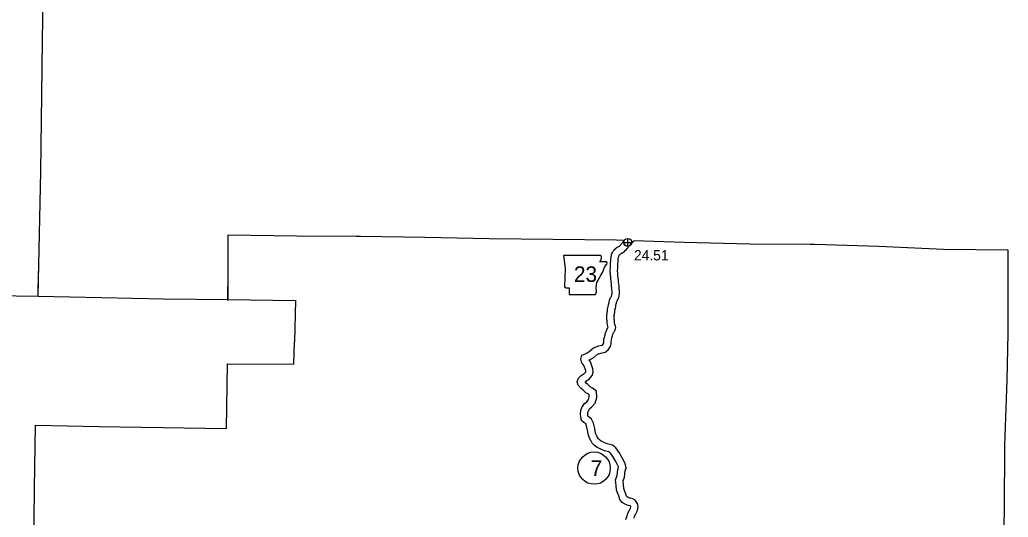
# Model space of a CAD drawing. Extents: x -939622 to -934245, y 1383184 to 1385301.
# Drawn here: x -936241.4 to -936120.4, y 1384764 to 1384824.9 of the extents above; entities that cross this region are included whole.
import ezdxf

# ---------------------------------------------------------------- set-up
doc = ezdxf.new("R2010")
doc.units = 0
for name, color, linetype in [('2', 7, 'Continuous'), ('Level 10', 7, 'Continuous'), ('Level 2', 7, 'Continuous'), ('Level 21', 7, 'Continuous'), ('Level 25', 7, 'Continuous'), ('Level 26', 7, 'Continuous'), ('Level 27', 7, 'Continuous')]:
    doc.layers.add(name, color=color, linetype=linetype)

msp = doc.modelspace()

# ---------------------------------------------------------------- linework, layer by layer
at = {"layer": '2'}
msp.add_lwpolyline([(-936255.7, 1384791.16), (-936244.58, 1384791.15), (-936239.18, 1384791.06), (-936238.82, 1384806.34), (-936238.71, 1384815.74), (-936238.65, 1384822.33), (-936238.51, 1384830.53), (-936234.63, 1384830.51), (-936234.25, 1384853.43)], dxfattribs=at)
at = {"layer": 'Level 10'}
for points in [[(-936169.88, 1384785.79), (-936169.74, 1384786.3), (-936169.71, 1384786.44), (-936169.67, 1384786.57), (-936169.61, 1384786.73), (-936169.57, 1384786.85), (-936169.52, 1384786.99), (-936169.45, 1384787.12), (-936169.38, 1384787.23), (-936169.36, 1384787.25), (-936169.4, 1384787.36), (-936169.46, 1384787.6), (-936169.47, 1384787.76), (-936169.49, 1384787.92), (-936169.5, 1384788.05), (-936169.51, 1384788.16), (-936169.53, 1384788.33), (-936169.53, 1384788.5), (-936169.52, 1384788.65), (-936169.51, 1384788.8), (-936169.48, 1384788.94), (-936169.47, 1384789.1), (-936169.45, 1384789.21), (-936169.44, 1384789.31), (-936169.42, 1384789.48), (-936169.39, 1384789.65), (-936169.35, 1384789.81), (-936169.32, 1384789.94), (-936169.3, 1384790.04), (-936169.28, 1384790.17), (-936169.25, 1384790.3), (-936169.22, 1384790.42), (-936169.18, 1384790.56), (-936169.15, 1384790.69), (-936169.1, 1384790.8), (-936169.04, 1384790.9), (-936169.01, 1384790.98), (-936168.97, 1384791.07), (-936168.93, 1384791.15), (-936168.91, 1384791.21), (-936168.89, 1384791.27), (-936168.88, 1384791.31), (-936168.88, 1384791.33), (-936168.88, 1384791.41), (-936168.88, 1384791.68), (-936168.89, 1384791.85), (-936168.92, 1384792.1), (-936168.93, 1384792.29), (-936168.94, 1384792.43), (-936168.96, 1384792.62), (-936168.99, 1384792.78), (-936169.01, 1384792.94), (-936169.02, 1384793.13), (-936169.03, 1384793.27), (-936169.05, 1384793.41), (-936169.07, 1384793.56), (-936169.08, 1384793.72), (-936169.09, 1384793.85), (-936169.1, 1384793.97), (-936169.12, 1384794.12), (-936169.11, 1384794.31), (-936169.09, 1384794.48), (-936169.08, 1384794.7), (-936169.06, 1384795.05), (-936169.03, 1384795.43), (-936169.02, 1384795.63), (-936169.01, 1384795.78), (-936168.99, 1384795.94), (-936168.96, 1384796.05), (-936168.93, 1384796.15), (-936168.9, 1384796.27), (-936168.84, 1384796.41), (-936168.75, 1384796.59), (-936168.63, 1384796.71), (-936168.55, 1384796.81), (-936168.44, 1384796.89), (-936168.4, 1384796.94), (-936168.28, 1384797.03), (-936168.18, 1384797.1), (-936168.09, 1384797.15), (-936167.99, 1384797.19), (-936167.98, 1384797.2), (-936167.95, 1384797.24), (-936167.86, 1384797.32), (-936167.8, 1384797.38), (-936167.76, 1384797.44), (-936167.7, 1384797.51), (-936167.64, 1384797.59), (-936167.58, 1384797.67), (-936167.51, 1384797.75), (-936167.45, 1384797.83), (-936167.4, 1384797.9)], [(-936168.99, 1384785.49), (-936168.9, 1384785.96), (-936168.87, 1384786.07), (-936168.84, 1384786.19), (-936168.81, 1384786.3), (-936168.76, 1384786.44), (-936168.73, 1384786.55), (-936168.7, 1384786.63), (-936168.68, 1384786.66), (-936168.64, 1384786.72), (-936168.59, 1384786.79), (-936168.56, 1384786.84), (-936168.53, 1384786.88), (-936168.47, 1384786.99), (-936168.45, 1384787.09), (-936168.44, 1384787.22), (-936168.46, 1384787.37), (-936168.53, 1384787.6), (-936168.57, 1384787.75), (-936168.58, 1384787.86), (-936168.6, 1384787.99), (-936168.6, 1384788.12), (-936168.62, 1384788.25), (-936168.63, 1384788.38), (-936168.63, 1384788.48), (-936168.62, 1384788.58), (-936168.61, 1384788.69), (-936168.59, 1384788.82), (-936168.58, 1384788.97), (-936168.55, 1384789.09), (-936168.54, 1384789.22), (-936168.53, 1384789.35), (-936168.51, 1384789.47), (-936168.47, 1384789.61), (-936168.44, 1384789.76), (-936168.41, 1384789.89), (-936168.4, 1384789.99), (-936168.38, 1384790.09), (-936168.35, 1384790.2), (-936168.32, 1384790.32), (-936168.3, 1384790.38), (-936168.28, 1384790.41), (-936168.24, 1384790.51), (-936168.19, 1384790.61), (-936168.15, 1384790.7), (-936168.1, 1384790.8), (-936168.06, 1384790.92), (-936168.03, 1384791.02), (-936168, 1384791.13), (-936167.98, 1384791.3), (-936167.98, 1384791.44), (-936167.98, 1384791.71), (-936168, 1384791.92), (-936168.02, 1384792.16), (-936168.03, 1384792.35), (-936168.04, 1384792.53), (-936168.08, 1384792.76), (-936168.1, 1384792.9), (-936168.11, 1384793.02), (-936168.13, 1384793.21), (-936168.14, 1384793.36), (-936168.16, 1384793.51), (-936168.17, 1384793.65), (-936168.19, 1384793.79), (-936168.19, 1384793.92), (-936168.21, 1384794.07), (-936168.22, 1384794.14), (-936168.21, 1384794.24), (-936168.19, 1384794.41), (-936168.18, 1384794.64), (-936168.16, 1384794.99), (-936168.13, 1384795.37), (-936168.12, 1384795.58), (-936168.12, 1384795.69), (-936168.11, 1384795.75), (-936168.09, 1384795.82), (-936168.07, 1384795.91), (-936168.05, 1384795.96), (-936168.02, 1384796.03), (-936168, 1384796.07), (-936167.96, 1384796.11), (-936167.92, 1384796.16), (-936167.85, 1384796.22), (-936167.8, 1384796.26), (-936167.76, 1384796.3), (-936167.72, 1384796.32), (-936167.67, 1384796.35), (-936167.6, 1384796.38), (-936167.48, 1384796.44), (-936167.35, 1384796.55), (-936167.27, 1384796.64), (-936167.22, 1384796.7), (-936167.13, 1384796.78), (-936167.05, 1384796.88), (-936166.99, 1384796.96), (-936166.92, 1384797.04), (-936166.87, 1384797.12), (-936166.81, 1384797.19), (-936166.74, 1384797.28), (-936166.69, 1384797.35)], [(-936168.91, 1384785.95), (-936168.9, 1384785.96), (-936168.87, 1384786.07), (-936168.84, 1384786.19), (-936168.81, 1384786.3), (-936168.76, 1384786.44), (-936168.73, 1384786.55), (-936168.7, 1384786.63), (-936168.68, 1384786.66), (-936168.64, 1384786.72), (-936168.59, 1384786.79), (-936168.56, 1384786.84), (-936168.53, 1384786.88), (-936168.47, 1384786.99), (-936168.45, 1384787.09), (-936168.44, 1384787.22), (-936168.46, 1384787.37), (-936168.53, 1384787.6), (-936168.57, 1384787.75), (-936168.58, 1384787.86), (-936168.6, 1384787.99), (-936168.6, 1384788.12), (-936168.62, 1384788.25), (-936168.63, 1384788.38), (-936168.63, 1384788.48), (-936168.62, 1384788.58), (-936168.61, 1384788.69), (-936168.59, 1384788.82), (-936168.58, 1384788.97), (-936168.55, 1384789.09), (-936168.54, 1384789.22), (-936168.53, 1384789.35), (-936168.51, 1384789.47), (-936168.47, 1384789.61), (-936168.44, 1384789.76), (-936168.41, 1384789.89), (-936168.4, 1384789.99), (-936168.38, 1384790.09), (-936168.35, 1384790.2), (-936168.32, 1384790.32), (-936168.3, 1384790.38), (-936168.28, 1384790.41), (-936168.24, 1384790.51), (-936168.19, 1384790.61), (-936168.15, 1384790.7), (-936168.1, 1384790.8), (-936168.06, 1384790.92), (-936168.03, 1384791.02), (-936168, 1384791.13), (-936167.98, 1384791.3), (-936167.98, 1384791.44), (-936167.98, 1384791.71), (-936168, 1384791.92), (-936168.02, 1384792.16), (-936168.03, 1384792.35), (-936168.04, 1384792.53), (-936168.08, 1384792.76), (-936168.1, 1384792.9), (-936168.11, 1384793.02), (-936168.13, 1384793.21), (-936168.14, 1384793.36), (-936168.16, 1384793.51), (-936168.17, 1384793.65), (-936168.19, 1384793.79), (-936168.19, 1384793.92), (-936168.21, 1384794.07), (-936168.22, 1384794.14), (-936168.21, 1384794.24), (-936168.19, 1384794.41), (-936168.18, 1384794.64), (-936168.16, 1384794.99), (-936168.13, 1384795.37), (-936168.12, 1384795.58), (-936168.12, 1384795.69), (-936168.11, 1384795.75), (-936168.09, 1384795.82), (-936168.07, 1384795.91), (-936168.05, 1384795.96), (-936168.02, 1384796.03), (-936168, 1384796.07), (-936167.96, 1384796.11), (-936167.92, 1384796.16), (-936167.85, 1384796.22), (-936167.8, 1384796.26), (-936167.76, 1384796.3), (-936167.72, 1384796.32), (-936167.67, 1384796.35), (-936167.6, 1384796.38), (-936167.48, 1384796.44), (-936167.35, 1384796.55), (-936167.27, 1384796.64), (-936167.22, 1384796.7), (-936167.13, 1384796.78), (-936167.05, 1384796.88), (-936166.99, 1384796.96), (-936166.92, 1384797.04), (-936166.87, 1384797.12), (-936166.81, 1384797.19), (-936166.74, 1384797.28), (-936166.69, 1384797.35)], [(-936167.41, 1384797.88), (-936167.41, 1384797.88)], [(-936166.67, 1384797.37), (-936166.62, 1384797.44), (-936166.58, 1384797.5), (-936166.55, 1384797.54), (-936166.54, 1384797.55), (-936166.22, 1384797.85)], [(-936166.67, 1384797.37), (-936166.62, 1384797.44), (-936166.58, 1384797.5), (-936166.55, 1384797.54), (-936166.54, 1384797.55), (-936166.54, 1384797.55)], [(-936169.09, 1384771.85), (-936169.25, 1384771.99), (-936169.33, 1384772), (-936169.81, 1384772.14), (-936170.16, 1384772.3), (-936170.43, 1384772.39), (-936170.69, 1384772.54), (-936171.05, 1384772.78), (-936171.3, 1384773.07), (-936171.48, 1384773.4), (-936171.63, 1384773.66), (-936171.76, 1384774.04), (-936171.87, 1384774.65), (-936172, 1384775.19), (-936172.11, 1384775.42), (-936172.33, 1384775.59), (-936172.61, 1384775.85), (-936172.72, 1384776.29), (-936172.76, 1384776.63), (-936172.71, 1384777.07), (-936172.58, 1384777.43), (-936172.27, 1384777.91), (-936171.98, 1384778.13), (-936171.77, 1384778.39), (-936171.67, 1384778.75), (-936171.68, 1384778.98), (-936171.77, 1384779.06), (-936172.09, 1384779.24), (-936172.47, 1384779.59), (-936172.72, 1384779.78), (-936173.02, 1384780.18), (-936173.14, 1384780.59), (-936173.01, 1384781.02), (-936172.66, 1384781.36), (-936172.29, 1384781.61), (-936172.1, 1384781.8), (-936172.09, 1384781.84), (-936172.11, 1384781.97), (-936172.32, 1384782.59), (-936172.4, 1384782.69), (-936172.57, 1384782.87), (-936172.72, 1384783.35), (-936172.57, 1384783.84), (-936172.19, 1384784.02), (-936171.95, 1384784.11), (-936171.67, 1384784.28), (-936171.14, 1384784.74), (-936170.5, 1384784.97), (-936170.12, 1384785.06), (-936170, 1384785.14), (-936169.92, 1384785.27), (-936169.89, 1384785.38), (-936169.9, 1384785.67), (-936169.88, 1384785.79)], [(-936168.44, 1384772.47), (-936168.83, 1384772.81), (-936169.11, 1384772.88), (-936169.5, 1384772.99), (-936169.83, 1384773.14), (-936170.07, 1384773.22), (-936170.22, 1384773.3), (-936170.44, 1384773.46), (-936170.56, 1384773.59), (-936170.69, 1384773.84), (-936170.8, 1384774.04), (-936170.89, 1384774.27), (-936170.99, 1384774.84), (-936171.15, 1384775.5), (-936171.39, 1384776), (-936171.74, 1384776.27), (-936171.8, 1384776.33), (-936171.83, 1384776.45), (-936171.85, 1384776.63), (-936171.83, 1384776.86), (-936171.77, 1384777.02), (-936171.6, 1384777.29), (-936171.34, 1384777.49), (-936170.95, 1384777.97), (-936170.76, 1384778.64), (-936170.8, 1384779.43), (-936171.26, 1384779.8), (-936171.55, 1384779.97), (-936171.89, 1384780.28), (-936172.07, 1384780.42), (-936172.18, 1384780.57), (-936172.1, 1384780.66), (-936171.7, 1384780.91), (-936171.3, 1384781.34), (-936171.18, 1384781.75), (-936171.22, 1384782.16), (-936171.52, 1384783.03), (-936171.69, 1384783.25), (-936171.55, 1384783.3), (-936171.13, 1384783.55), (-936170.68, 1384783.95), (-936170.25, 1384784.1), (-936169.73, 1384784.22), (-936169.34, 1384784.51), (-936169.08, 1384784.9), (-936168.99, 1384785.27), (-936168.99, 1384785.49)], [(-936166.19, 1384763.89), (-936166.12, 1384764.14), (-936165.95, 1384764.41), (-936165.75, 1384764.82), (-936165.68, 1384765.23), (-936165.72, 1384765.58), (-936165.83, 1384765.81), (-936166.04, 1384766.07), (-936166.34, 1384766.23), (-936166.62, 1384766.31), (-936166.74, 1384766.34), (-936166.89, 1384766.41), (-936167.04, 1384766.48), (-936167.1, 1384766.58), (-936167.22, 1384766.94), (-936167.37, 1384767.28), (-936167.44, 1384767.5), (-936167.47, 1384767.96), (-936167.54, 1384768.46), (-936167.35, 1384768.9), (-936167.29, 1384769.66), (-936167.17, 1384770.05), (-936167.27, 1384770.57), (-936167.64, 1384771.25), (-936168.01, 1384771.93), (-936168.44, 1384772.47)], [(-936167.19, 1384763.71), (-936167.05, 1384764.15), (-936166.95, 1384764.5), (-936166.74, 1384764.84), (-936166.62, 1384765.1), (-936166.59, 1384765.26), (-936166.6, 1384765.34), (-936166.62, 1384765.36), (-936166.68, 1384765.39), (-936166.85, 1384765.44), (-936167.03, 1384765.48), (-936167.29, 1384765.6), (-936167.64, 1384765.78), (-936167.92, 1384766.17), (-936168.06, 1384766.62), (-936168.21, 1384766.96), (-936168.33, 1384767.33), (-936168.36, 1384767.87), (-936168.46, 1384768.59), (-936168.24, 1384769.12), (-936168.18, 1384769.83), (-936168.1, 1384770.1), (-936168.13, 1384770.26), (-936168.43, 1384770.81), (-936168.77, 1384771.43), (-936169.09, 1384771.85)]]:
    msp.add_lwpolyline(points, dxfattribs=at)
at = {"layer": 'Level 2'}
for points in [[(-936200.16, 1384798.36), (-936207.5, 1384798.43), (-936215.93, 1384798.54), (-936215.94, 1384790.65)], [(-936167.5, 1384797.89), (-936168.34, 1384797.92), (-936176.15, 1384798), (-936183.92, 1384798.08), (-936191.76, 1384798.24), (-936199.64, 1384798.37), (-936200.16, 1384798.36)], [(-936144.62, 1384797.37), (-936152.02, 1384797.44), (-936160.07, 1384797.62), (-936166.17, 1384797.84)], [(-936120.36, 1384786.55), (-936120.37, 1384796.69), (-936128.29, 1384796.79), (-936136.2, 1384797.14), (-936144.05, 1384797.37), (-936144.62, 1384797.37)], [(-936255.7, 1384791.16), (-936244.58, 1384791.15), (-936239.18, 1384791.06), (-936239.11, 1384794.11)], [(-936215.94, 1384790.54), (-936215.89, 1384794)], [(-936239.18, 1384791.06), (-936231.41, 1384790.91), (-936223.8, 1384790.73), (-936215.94, 1384790.65), (-936207.66, 1384790.55), (-936207.77, 1384785.45)], [(-936219.36, 1384790.68), (-936215.94, 1384790.65), (-936207.66, 1384790.55), (-936207.77, 1384785.45)], [(-936121.11, 1384747.88), (-936121.1, 1384749.17), (-936120.98, 1384757.08), (-936120.84, 1384764.93), (-936120.77, 1384772.79), (-936120.51, 1384780.78), (-936120.36, 1384786.55)], [(-936255.14, 1384736.38), (-936248.04, 1384736.19), (-936247.89, 1384744.06), (-936247.76, 1384751.98), (-936247.65, 1384759.88), (-936239.71, 1384759.57), (-936239.6, 1384767.53), (-936239.51, 1384775.26), (-936231.73, 1384775.11), (-936223.87, 1384774.96), (-936216.11, 1384774.84), (-936215.97, 1384782.76), (-936207.84, 1384782.72), (-936207.77, 1384785.45)], [(-936255.14, 1384736.38), (-936248.04, 1384736.19), (-936247.89, 1384744.06), (-936247.76, 1384751.98), (-936247.65, 1384759.88), (-936239.71, 1384759.57), (-936239.6, 1384767.53), (-936239.51, 1384775.26), (-936231.73, 1384775.11), (-936223.87, 1384774.96), (-936216.11, 1384774.84), (-936215.97, 1384782.76), (-936207.84, 1384782.72), (-936207.77, 1384785.45)]]:
    msp.add_lwpolyline(points, dxfattribs=at)
at = {"layer": 'Level 21'}
msp.add_lwpolyline([(-936174.83, 1384796.03), (-936174.61, 1384794.51), (-936174.71, 1384792.2), (-936174.5, 1384792.08), (-936174.12, 1384792.08), (-936174.12, 1384791.26), (-936170.93, 1384791.26), (-936170.77, 1384791.59), (-936170.82, 1384792.13), (-936170.75, 1384792.73), (-936170.47, 1384793.22), (-936170.29, 1384793.57), (-936170.04, 1384793.95), (-936169.89, 1384794.36), (-936169.76, 1384794.69), (-936169.53, 1384794.97), (-936169.48, 1384795.15), (-936169.58, 1384795.27), (-936170.37, 1384795.27), (-936170.19, 1384795.63), (-936170.16, 1384795.86), (-936170.27, 1384796.03)], close=True, dxfattribs=at)
at = {"layer": 'Level 26'}
for p, q in [((-936167.44, 1384797.63), (-936166.47, 1384797.65)), ((-936166.94, 1384797.15), (-936166.97, 1384798.13))]:
    msp.add_line(p, q, dxfattribs=at)
msp.add_circle((-936166.96, 1384797.64), 0.488, dxfattribs=at)
at = {"layer": 'Level 27'}
msp.add_circle((-936171.08, 1384770), 1.98, dxfattribs=at)

# ---------------------------------------------------------------- texts
at = {"layer": 'Level 21'}
msp.add_text('23', height=1.901, dxfattribs=at).set_placement((-936173.55, 1384792.81))
at = {"layer": 'Level 25'}
msp.add_text('24.51', height=1.267, dxfattribs=at).set_placement((-936166.2, 1384795.44))
at = {"layer": 'Level 27'}
msp.add_text('7', height=1.9, dxfattribs=at).set_placement((-936171.5, 1384769.05))

doc.saveas('drawing.dxf')
